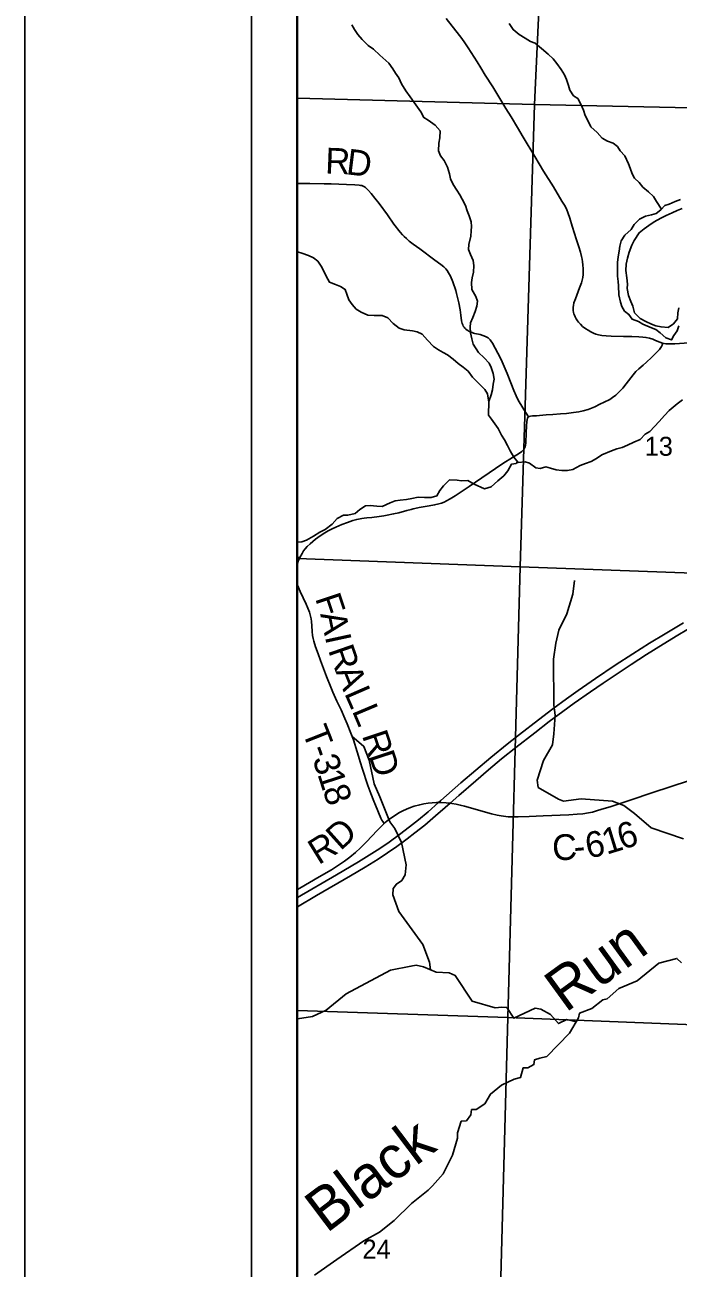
# Model space of a CAD drawing. Extents: x 0 to 34, y 0 to 22.
# Drawn here: x 2 to 3.441, y 16.998 to 19.741 of the extents above; entities that cross this region are included whole.
import ezdxf

# ---------------------------------------------------------------- set-up
doc = ezdxf.new("R2010")
doc.units = 0
for name, color, linetype in [('GM_X_County', 7, 'Continuous'), ('GM_X_County_Road', 7, 'Continuous'), ('GM_X_County_Road_Text', 7, 'Continuous'), ('GM_X_Minor_River', 7, 'Continuous'), ('GM_X_Minor_River_Text', 7, 'Continuous'), ('GM_X_Section', 7, 'Continuous'), ('GM_X_Section_Text', 7, 'Continuous'), ('GM_X_State_Route', 7, 'Continuous'), ('GM_X_Township', 7, 'Continuous'), ('GM_X_Township_Road', 7, 'Continuous'), ('GM_X_Township_Road_Text', 7, 'Continuous'), ('SH_Border', 7, 'Continuous'), ('SH_Data', 7, 'Continuous')]:
    doc.layers.add(name, color=color, linetype=linetype)

msp = doc.modelspace()

# ---------------------------------------------------------------- linework, layer by layer
at = {"layer": 'GM_X_County'}
msp.add_lwpolyline([(7.0736, 21.2003), (2.6013, 21.2003), (2.6013, 14.4003), (9.4013, 14.4003), (9.4013, 21.1598)], dxfattribs=at)
at = {"layer": 'GM_X_County_Road'}
for points in [[(2.9295, 19.7551), (2.9428, 19.7379), (2.9619, 19.7134), (2.9692, 19.7034), (2.9779, 19.6905), (2.9846, 19.6801), (2.9979, 19.6591), (3.0061, 19.646), (3.0157, 19.6301), (3.0321, 19.6038), (3.0496, 19.575), (3.0611, 19.5564), (3.0724, 19.5382), (3.0867, 19.5143), (3.0993, 19.4934), (3.1246, 19.4503), (3.1438, 19.4182), (3.1661, 19.3834), (3.1848, 19.3521), (3.1915, 19.341), (3.1957, 19.3328), (3.1979, 19.3268), (3.2023, 19.314), (3.2071, 19.2969), (3.2122, 19.2803), (3.2159, 19.2684), (3.2217, 19.2508), (3.2256, 19.239), (3.228, 19.23), (3.2293, 19.224), (3.2303, 19.2178), (3.231, 19.2117), (3.2315, 19.2023), (3.2316, 19.1961), (3.2312, 19.1898), (3.2305, 19.1836), (3.2292, 19.1775), (3.2275, 19.1719), (3.2236, 19.1605), (3.2147, 19.1363), (3.2113, 19.1273), (3.21, 19.1216), (3.2096, 19.1179), (3.2094, 19.1143), (3.2094, 19.1105), (3.2102, 19.1063), (3.2112, 19.1029), (3.2123, 19.1002), (3.2139, 19.0964), (3.2161, 19.0923), (3.2176, 19.0897), (3.2191, 19.0876), (3.2213, 19.0847), (3.2254, 19.0802), (3.2302, 19.0756), (3.2371, 19.0703), (3.2425, 19.0669), (3.2484, 19.0632), (3.2544, 19.0603), (3.2597, 19.0584), (3.2654, 19.0568), (3.2729, 19.0556), (3.2821, 19.0547), (3.2934, 19.0542), (3.3207, 19.0535), (3.3388, 19.0529), (3.3542, 19.0522), (3.3628, 19.0521), (3.37, 19.0513), (3.3778, 19.0495), (3.3852, 19.0471), (3.3912, 19.0445), (3.4005, 19.0405), (3.4065, 19.0384), (3.4074, 19.0382)], [(3.4074, 19.0382), (3.4138, 19.0371), (3.4197, 19.0369), (3.4259, 19.0371), (3.4336, 19.0374), (3.4746, 19.0397)], [(3.1436, 17.9953), (3.1996, 17.9978), (3.2183, 17.999), (3.2306, 18.0004), (3.243, 18.0023), (3.2522, 18.0041), (3.2612, 18.0065), (3.273, 18.0102), (3.2908, 18.0158), (3.3439, 18.0333), (3.3763, 18.044), (3.4324, 18.0627), (3.4797, 18.0779), (3.5149, 18.0901), (3.5266, 18.0945), (3.5349, 18.0983)], [(2.7928, 17.9787), (2.795, 17.9807), (2.8021, 17.9865), (2.8096, 17.9921), (2.8172, 17.9973), (2.8252, 18.0021), (2.8334, 18.0064), (2.8418, 18.0104), (2.8503, 18.0138), (2.8591, 18.0168), (2.871, 18.0202), (2.8801, 18.0221), (2.8893, 18.0236), (2.8985, 18.0245), (2.9078, 18.025), (2.9124, 18.025), (2.9125, 18.025), (2.9172, 18.025), (2.9296, 18.0243), (2.9378, 18.0233), (2.9421, 18.0228), (2.9513, 18.0213), (2.9605, 18.0195), (2.9695, 18.0171), (3.0294, 18.0004), (3.0415, 17.9974), (3.0507, 17.9957), (3.0661, 17.9938), (3.0754, 17.9932), (3.0879, 17.9931), (3.1127, 17.994), (3.1436, 17.9953)], [(2.6013, 17.8328), (2.6064, 17.8357), (2.6494, 17.8607), (2.6761, 17.8766), (2.6919, 17.8866), (2.7047, 17.8954), (2.7171, 17.9048), (2.7291, 17.9148), (2.7406, 17.9253), (2.7538, 17.9384), (2.7773, 17.9633), (2.7881, 17.9744), (2.7928, 17.9787)]]:
    msp.add_lwpolyline(points, dxfattribs=at)
at = {"layer": 'GM_X_Minor_River'}
for points in [[(2.9365, 19.412), (2.9326, 19.4268), (2.9246, 19.4415), (2.9169, 19.4518), (2.9127, 19.4631), (2.9134, 19.4798), (2.9153, 19.4916), (2.916, 19.5068), (2.9053, 19.5197), (2.8893, 19.5303), (2.8798, 19.5363), (2.8733, 19.5492), (2.8588, 19.5696), (2.85, 19.5821), (2.8405, 19.595), (2.8309, 19.6109), (2.8252, 19.6238), (2.8179, 19.6344), (2.8114, 19.6439), (2.8026, 19.656), (2.7828, 19.6742), (2.7687, 19.687), (2.757, 19.6953), (2.7444, 19.7086), (2.7345, 19.7196), (2.7272, 19.7305), (2.7211, 19.7412)], [(3.4044, 19.3345), (3.3932, 19.3512), (3.3867, 19.3618), (3.376, 19.3728), (3.363, 19.383), (3.355, 19.3929), (3.3448, 19.4027), (3.3398, 19.4125), (3.3352, 19.4243), (3.3317, 19.4345), (3.3233, 19.4516), (3.313, 19.463), (3.3069, 19.4728), (3.2974, 19.48), (3.2852, 19.4841), (3.2731, 19.4909), (3.2624, 19.5034), (3.2487, 19.5159), (3.2418, 19.5299), (3.2357, 19.5409), (3.2322, 19.5523), (3.2265, 19.5659), (3.22, 19.5781), (3.2101, 19.5845), (3.202, 19.5966), (3.199, 19.6068), (3.1947, 19.6201), (3.1905, 19.6303), (3.1833, 19.6421), (3.1733, 19.6553), (3.1653, 19.6656), (3.1543, 19.6762), (3.1398, 19.689), (3.1253, 19.7004), (3.1155, 19.7041), (3.1037, 19.7113), (3.0904, 19.7196), (3.077, 19.7306), (3.0683, 19.7435)], [(3.4507, 18.9137), (3.439, 18.9045), (3.4216, 18.8897), (3.4107, 18.8786), (3.399, 18.866), (3.3888, 18.8546), (3.3786, 18.8436), (3.3683, 18.8375), (3.3574, 18.8257), (3.343, 18.8199), (3.329, 18.8134), (3.3176, 18.8085), (3.3055, 18.8054), (3.2938, 18.8012), (3.2725, 18.792), (3.2608, 18.7843), (3.2491, 18.7775), (3.237, 18.7733), (3.2252, 18.7687), (3.2089, 18.7595), (3.1968, 18.7579), (3.1843, 18.7575), (3.1721, 18.7594), (3.1596, 18.7631), (3.1493, 18.7657), (3.1368, 18.7619), (3.127, 18.7638), (3.1133, 18.774), (3.1034, 18.7766), (3.0878, 18.775), (3.0787, 18.7868), (3.0703, 18.8012), (3.0645, 18.8129), (3.0577, 18.825), (3.0512, 18.8357), (3.0439, 18.8504), (3.0366, 18.8603), (3.0294, 18.8705), (3.0229, 18.88), (3.0235, 18.91), (3.0288, 18.9248), (3.0318, 18.9354), (3.0332, 18.948), (3.0355, 18.9594), (3.0331, 18.9719), (3.0285, 18.9852), (3.0243, 18.9946), (3.0133, 19.006), (3.0007, 19.0181), (2.9889, 19.0363), (2.9858, 19.0484), (2.9831, 19.0613), (2.9826, 19.0738), (2.9833, 19.0833), (2.9882, 19.0955), (2.9931, 19.1081), (2.9972, 19.1202), (2.9987, 19.1312), (2.9949, 19.1418), (2.9861, 19.1566), (2.9849, 19.1722), (2.9864, 19.1824), (2.9897, 19.195), (2.99, 19.2098), (2.9888, 19.2208), (2.9831, 19.2341), (2.9785, 19.2451), (2.9792, 19.2561), (2.9841, 19.2747), (2.9848, 19.2861), (2.9855, 19.2963), (2.9847, 19.3066), (2.9801, 19.3195), (2.9759, 19.3305), (2.9717, 19.3422), (2.9644, 19.3562), (2.9598, 19.3661), (2.9525, 19.3763), (2.9449, 19.3885), (2.9388, 19.401), (2.9365, 19.412)], [(3.4459, 19.3552), (3.4345, 19.3514), (3.4213, 19.3452), (3.4118, 19.3425), (3.4027, 19.3326), (3.3925, 19.3243), (3.3819, 19.3216), (3.369, 19.3185), (3.3561, 19.3124), (3.3437, 19.3002), (3.3376, 19.2892), (3.3236, 19.277), (3.3157, 19.2644), (3.3124, 19.2526), (3.3113, 19.2416), (3.3091, 19.2287), (3.3076, 19.2165), (3.3069, 19.2067), (3.3069, 19.1957), (3.3073, 19.1862)], [(3.4427, 19.1164), (3.4401, 19.1054), (3.4398, 19.0921), (3.4307, 19.081), (3.419, 19.0734), (3.4034, 19.0745), (3.392, 19.0771), (3.3825, 19.0801), (3.37, 19.0861), (3.3574, 19.0933), (3.3448, 19.1058), (3.341, 19.1202), (3.3364, 19.1305), (3.3314, 19.1437), (3.3287, 19.1589), (3.3294, 19.1688), (3.3282, 19.1828), (3.3255, 19.1988), (3.3262, 19.2132), (3.3296, 19.2261), (3.3333, 19.239), (3.3389, 19.2546), (3.3438, 19.2653), (3.3547, 19.282), (3.3661, 19.2911), (3.3767, 19.2984), (3.388, 19.306), (3.4032, 19.314), (3.4149, 19.3205), (3.4278, 19.3259), (3.4388, 19.3316), (3.4501, 19.3358)], [(3.0235, 18.9081), (3.0208, 18.9267), (3.0143, 18.9365), (3.001, 18.9501), (2.9876, 18.9634), (2.9781, 18.9766), (2.9667, 18.9857), (2.956, 18.9937), (2.945, 19.0035), (2.9324, 19.0129), (2.9229, 19.0178), (2.9123, 19.0235), (2.9012, 19.0314), (2.8883, 19.0451), (2.8765, 19.0583), (2.8654, 19.0636), (2.8548, 19.0654), (2.837, 19.068), (2.8259, 19.0714), (2.8122, 19.082), (2.8004, 19.0945), (2.7879, 19.0998), (2.7708, 19.0993), (2.7564, 19.1004), (2.7416, 19.1068), (2.7309, 19.1136), (2.7218, 19.1242), (2.7145, 19.1341), (2.7099, 19.1466), (2.7064, 19.1572), (2.6966, 19.1636), (2.6855, 19.1681), (2.6719, 19.173), (2.6646, 19.1863), (2.6604, 19.1962), (2.6539, 19.2083), (2.6462, 19.2193), (2.6367, 19.2268), (2.6257, 19.2321), (2.6109, 19.237), (2.6013, 19.2403)], [(3.3073, 19.1862), (3.3085, 19.1744), (3.3093, 19.1649), (3.3102, 19.1452), (3.3136, 19.1289), (3.3171, 19.1194), (3.3224, 19.1095), (3.3323, 19.102), (3.3396, 19.0914), (3.3537, 19.0865), (3.3632, 19.0808), (3.3822, 19.0725), (3.3917, 19.0688), (3.4012, 19.0616), (3.4141, 19.0502), (3.4267, 19.0457), (3.4316, 19.0556), (3.4387, 19.0659), (3.4429, 19.0765)], [(3.0866, 18.7766), (3.0837, 18.7727), (3.0738, 18.7716), (3.0655, 18.7567), (3.0565, 18.7461), (3.0436, 18.7346), (3.0285, 18.7213), (3.0137, 18.7171), (2.9913, 18.7276), (2.9772, 18.7356), (2.9632, 18.7348), (2.9537, 18.7362), (2.937, 18.7369), (2.9234, 18.7236), (2.9151, 18.7133), (2.909, 18.7019), (2.8962, 18.6977), (2.8817, 18.698), (2.8677, 18.6984), (2.8537, 18.696), (2.8415, 18.6933), (2.8275, 18.6925), (2.8169, 18.691), (2.8055, 18.6864), (2.7885, 18.6784), (2.7763, 18.6787), (2.7615, 18.6806), (2.7517, 18.6798), (2.7388, 18.6714), (2.7286, 18.6626), (2.7123, 18.6587), (2.7028, 18.6591), (2.6892, 18.6518), (2.6779, 18.6393), (2.6627, 18.6275), (2.651, 18.6213), (2.6366, 18.6126), (2.6211, 18.6038), (2.6109, 18.6003), (2.6013, 18.5997)], [(3.4526, 17.9447), (3.3812, 17.9695), (3.3448, 18.0009), (3.3216, 18.0183), (3.2962, 18.0281), (3.2268, 18.0332), (3.1882, 18.0281), (3.1772, 18.0323), (3.132, 18.0583), (3.13, 18.0746), (3.1439, 18.1175), (3.1639, 18.1525), (3.1668, 18.1767), (3.1697, 18.2177), (3.167, 18.2397), (3.1659, 18.3414), (3.1715, 18.3763), (3.1778, 18.4055), (3.1952, 18.4416), (3.2087, 18.4849), (3.2127, 18.5149)], [(2.8949, 17.6561), (2.8922, 17.6725), (2.8781, 17.7116), (2.8252, 17.7846), (2.8118, 17.821), (2.8121, 17.835), (2.8197, 17.8449), (2.8314, 17.8529), (2.8389, 17.8654), (2.8408, 17.8875), (2.8307, 17.9367), (2.8159, 17.9678), (2.8052, 17.9826), (2.783, 18.0375), (2.7704, 18.0663), (2.7593, 18.1186), (2.7478, 18.1489), (2.7216, 18.1716)], [(3.2158, 17.5408), (3.1958, 17.546), (3.1773, 17.5372), (3.1598, 17.5573), (3.1385, 17.569), (3.126, 17.5712), (3.0783, 17.5491), (3.0631, 17.5729), (3.0521, 17.5733), (3.0373, 17.5717), (2.9865, 17.5867), (2.9492, 17.6435), (2.9363, 17.6495), (2.9075, 17.651), (2.879, 17.6626), (2.8631, 17.666), (2.8517, 17.6637), (2.8063, 17.6548), (2.7091, 17.6029), (2.6645, 17.5671), (2.6342, 17.553), (2.6013, 17.5477)], [(3.4481, 17.6712), (3.4383, 17.6811), (3.3981, 17.6707), (3.3505, 17.6319), (3.31, 17.6147), (3.2847, 17.5922), (3.2749, 17.5895), (3.251, 17.5709), (3.2238, 17.5605), (3.2212, 17.5503), (3.2016, 17.5161), (3.1513, 17.4643), (3.1362, 17.4613), (3.1245, 17.4574), (3.123, 17.4468), (3.1094, 17.4399), (3.0991, 17.4395), (3.0935, 17.4186), (3.0791, 17.4148), (3.0515, 17.4014), (3.0269, 17.3816), (3.0145, 17.3604), (2.9956, 17.3478), (2.9854, 17.3474), (2.9839, 17.336), (2.9741, 17.3227), (2.9627, 17.3219), (2.9541, 17.2961), (2.9545, 17.2843), (2.9436, 17.2471), (2.9229, 17.2061), (2.8995, 17.1791), (2.8893, 17.1699), (2.853, 17.1406), (2.8149, 17.1026), (2.7824, 17.0767), (2.7476, 17.0576), (2.6882, 17.0164), (2.6391, 16.9821)]]:
    msp.add_lwpolyline(points, dxfattribs=at)
at = {"layer": 'GM_X_Section'}
for p, q in [((2.6013, 20.5903), (2.6013, 19.5793)), ((2.6013, 19.5793), (2.6013, 18.5632)), ((2.6013, 18.5632), (2.6013, 17.5659)), ((2.6013, 17.5659), (2.6013, 16.5373))]:
    msp.add_line(p, q, dxfattribs=at)
for points in [[(2.6013, 19.5793), (3.1241, 19.5651), (3.1703, 20.5686), (2.6013, 20.5903)], [(2.6013, 18.5632), (3.0927, 18.5447), (3.1241, 19.5651), (2.6013, 19.5793)], [(2.6013, 17.5659), (3.0654, 17.5504), (3.0927, 18.5447), (2.6013, 18.5632)], [(2.6013, 16.5373), (3.0372, 16.514), (3.0654, 17.5504), (2.6013, 17.5659)]]:
    msp.add_lwpolyline(points, dxfattribs=at)
for points in [[(3.1703, 20.5686), (3.6876, 20.5473), (3.6799, 20.3833), (3.6562, 19.8796), (3.6414, 19.554), (3.1241, 19.5651)], [(3.1241, 19.5651), (3.6414, 19.554), (3.6343, 19.3746), (3.6142, 18.8692), (4.1194, 18.8444), (4.1166, 18.5074), (3.0927, 18.5447)], [(4.1166, 18.5074), (4.0746, 17.5111), (3.0654, 17.5504), (3.0927, 18.5447)], [(3.0654, 17.5504), (4.0746, 17.5111), (4.0244, 16.4784), (4.0204, 16.4785), (3.5484, 16.5002), (3.0372, 16.514)]]:
    msp.add_lwpolyline(points, close=True, dxfattribs=at)
at = {"layer": 'GM_X_State_Route'}
for points in [[(2.6013, 17.8156), (2.6876, 17.8657), (2.7359, 17.8939), (2.7598, 17.9085), (2.7833, 17.9237), (2.8038, 17.9378), (2.8264, 17.9542), (2.8486, 17.9712), (2.868, 17.9868), (2.8894, 18.0048), (2.9124, 18.025), (2.9174, 18.0294), (2.9617, 18.0683), (2.9947, 18.0966), (3.028, 18.1246), (3.0641, 18.154), (3.0909, 18.1753), (3.1327, 18.2075), (3.1649, 18.2318), (3.195, 18.2538), (3.2203, 18.2719), (3.2586, 18.2983), (3.3023, 18.3278), (3.3413, 18.3532), (3.3781, 18.3764), (3.4125, 18.3974), (3.4525, 18.4212)], [(2.9268, 18.0137), (2.9378, 18.0233), (2.9572, 18.0403), (2.9945, 18.0731), (3.0228, 18.0974), (3.0515, 18.1212), (3.0831, 18.1464), (3.1247, 18.179), (3.1568, 18.2035), (3.1867, 18.2258), (3.2119, 18.2439), (3.2474, 18.2691), (3.2755, 18.2885), (3.3375, 18.3298), (3.3714, 18.3517), (3.4082, 18.3747), (3.4401, 18.3941), (3.4803, 18.4176)], [(2.6013, 17.7952), (2.6431, 17.8196), (2.7182, 17.8635), (2.7503, 17.8824), (2.7794, 17.9004), (2.8001, 17.914), (2.8205, 17.9281), (2.8431, 17.9446), (2.8603, 17.9578), (2.8821, 17.9754), (2.9058, 17.9953), (2.9268, 18.0137)]]:
    msp.add_lwpolyline(points, dxfattribs=at)
at = {"layer": 'GM_X_Township'}
msp.add_lwpolyline([(6.2234, 21.2003), (2.6013, 21.2003), (2.6013, 16.5379)], dxfattribs=at)
at = {"layer": 'GM_X_Township_Road'}
for points in [[(2.6013, 19.3907), (2.6289, 19.3906), (2.6599, 19.3901), (2.6754, 19.3899), (2.7095, 19.3888), (2.7281, 19.388), (2.7374, 19.3871), (2.7405, 19.3867), (2.7435, 19.3861), (2.7463, 19.3851), (2.749, 19.3838), (2.7516, 19.382), (2.7539, 19.38), (2.7581, 19.3755), (2.7641, 19.3685), (2.7718, 19.3588), (2.7814, 19.3465), (2.7999, 19.3217), (2.8142, 19.3014), (2.8282, 19.2831), (2.833, 19.2779), (2.8368, 19.2737), (2.8415, 19.2695), (2.848, 19.2639), (2.8563, 19.2573), (2.8711, 19.2464), (2.9046, 19.222), (2.9178, 19.212), (2.9244, 19.2068), (2.9283, 19.2028), (2.9314, 19.199), (2.9348, 19.194), (2.9386, 19.1861), (2.9439, 19.1736), (2.9503, 19.155), (2.9524, 19.1483), (2.9545, 19.1396), (2.9572, 19.1276), (2.9599, 19.1124), (2.9617, 19.1003), (2.9634, 19.0881), (2.9648, 19.0821), (2.9658, 19.0792), (2.9671, 19.0764), (2.9687, 19.0738), (2.9707, 19.0714), (2.9729, 19.0693), (2.9755, 19.0675), (2.9809, 19.0645), (2.9865, 19.0618), (2.9894, 19.0607), (2.9924, 19.0598), (3.0045, 19.0573), (3.0105, 19.0557), (3.0163, 19.0534), (3.0191, 19.052), (3.0217, 19.0503), (3.024, 19.0483), (3.0262, 19.0461), (3.0281, 19.0436), (3.0313, 19.0384), (3.0434, 19.0167), (3.049, 19.0056), (3.0529, 18.9972), (3.0636, 18.9713), (3.0717, 18.9512), (3.0785, 18.9338), (3.0835, 18.9225), (3.0892, 18.9115), (3.0939, 18.9034), (3.1009, 18.892), (3.1112, 18.8759)], [(3.1112, 18.8759), (3.1121, 18.8765), (3.1156, 18.8776), (3.1197, 18.878), (3.1286, 18.8783), (3.1355, 18.8786), (3.1496, 18.8801), (3.1647, 18.8815), (3.1813, 18.8826), (3.1948, 18.8836), (3.21, 18.8853), (3.2219, 18.8871), (3.2314, 18.889), (3.2425, 18.8924), (3.25, 18.895), (3.2574, 18.8984), (3.2684, 18.9039), (3.2778, 18.9087), (3.2901, 18.9146), (3.2962, 18.9185), (3.3035, 18.924), (3.3082, 18.9281), (3.3126, 18.9325), (3.3188, 18.9394), (3.3267, 18.949), (3.342, 18.9686), (3.348, 18.9757), (3.3546, 18.9822), (3.3641, 18.9902), (3.3711, 18.9963), (3.3826, 19.0067), (3.3913, 19.0155), (3.3996, 19.0247), (3.403, 19.0288), (3.4046, 19.0314), (3.406, 19.0343), (3.4074, 19.0382)], [(2.6069, 18.566), (2.6114, 18.5746), (2.6145, 18.58), (2.6182, 18.585), (2.6224, 18.5896), (2.6292, 18.5959), (2.6412, 18.6058), (2.6511, 18.6132), (2.6615, 18.62), (2.6694, 18.6248), (2.6777, 18.629), (2.6862, 18.6329), (2.6995, 18.6385), (2.7116, 18.6432), (2.7236, 18.6474), (2.7322, 18.6495), (2.7433, 18.6518), (2.7488, 18.6527), (2.7544, 18.6531), (2.7651, 18.6541), (2.7815, 18.6561), (2.7916, 18.6578), (2.7991, 18.6591), (2.8132, 18.6617), (2.8248, 18.6643), (2.8428, 18.6692), (2.852, 18.6719), (2.8564, 18.6731), (2.8603, 18.674), (2.8701, 18.676), (2.8916, 18.6794), (2.9038, 18.6816), (2.9129, 18.6837), (2.9188, 18.6855), (2.9246, 18.6878), (2.9302, 18.6905), (2.9384, 18.695), (2.949, 18.7015), (2.9799, 18.7223), (3.0083, 18.7414), (3.0546, 18.7727), (3.0753, 18.7865), (3.0912, 18.7962), (3.0964, 18.7997), (3.0988, 18.8016), (3.1009, 18.8039), (3.1024, 18.8066), (3.1034, 18.8095), (3.1041, 18.8126), (3.1048, 18.8187), (3.1055, 18.8405), (3.1064, 18.856), (3.1074, 18.8652), (3.1082, 18.8701), (3.109, 18.8727), (3.11, 18.875), (3.1112, 18.8759)], [(2.6069, 18.566), (2.6013, 18.5662)], [(2.6013, 18.5521), (2.6013, 18.5523), (2.6032, 18.5576), (2.6051, 18.5624), (2.6069, 18.566)], [(2.7928, 17.9787), (2.7893, 17.9832), (2.7875, 17.9861), (2.7852, 17.9906), (2.7734, 18.0192), (2.7699, 18.0278), (2.7631, 18.0452), (2.7568, 18.0627), (2.7442, 18.1011), (2.7405, 18.1129), (2.7329, 18.1365), (2.7246, 18.1632), (2.7193, 18.1778), (2.7108, 18.1985), (2.7057, 18.2101), (2.6975, 18.2292), (2.6884, 18.2488), (2.6794, 18.2684), (2.6746, 18.2799), (2.6654, 18.303), (2.6523, 18.3386), (2.6469, 18.3534), (2.6412, 18.3682), (2.6372, 18.3812), (2.6356, 18.3871), (2.6346, 18.3932), (2.6337, 18.4025), (2.6331, 18.4149), (2.6324, 18.4242), (2.6316, 18.4304), (2.6303, 18.4364), (2.6276, 18.4453), (2.6243, 18.454), (2.6206, 18.4625), (2.6138, 18.4765), (2.607, 18.4905), (2.6034, 18.4991), (2.6013, 18.5049), (2.6013, 18.5051)]]:
    msp.add_lwpolyline(points, dxfattribs=at)
at = {"layer": 'SH_Border'}
msp.add_lwpolyline([(2, 21.5), (33.5, 21.5), (33.5, 0.5), (2, 0.5)], close=True, dxfattribs=at)
at = {"layer": 'SH_Data'}
for p, q in [((2.5, 21.2997), (2.5, 14.2997)), ((2.6, 21.1997), (2.6, 14.3997))]:
    msp.add_line(p, q, dxfattribs=at)

# ---------------------------------------------------------------- texts
at = {"layer": 'GM_X_County_Road_Text'}
for s, rotation, p in [('D', 41.8479, (2.6961, 17.9173)), ('1', 17.0302, (3.2831, 17.9096)), ('6', 18.112, (3.3174, 17.9202)), ('R', 31.7543, (2.6479, 17.8864)), ('C', 2.7241, (3.1644, 17.8969)), ('6', 9.9535, (3.2414, 17.9018)), ('-', 4.6927, (3.2128, 17.8992))]:
    msp.add_text(s, height=0.0568, rotation=rotation, dxfattribs=at).set_placement(p)
at = {"layer": 'GM_X_Minor_River_Text'}
for s, rotation, p in [('Run', 36.0258, (3.1926, 17.56)), ('Black', 37.0269, (2.6653, 17.0734))]:
    msp.add_text(s, height=0.0947, rotation=rotation, dxfattribs=at).set_placement(p)
at = {"layer": 'GM_X_Section_Text'}
for s, p in [('13', (3.3672, 18.7901)), ('24', (2.7447, 17.0187))]:
    msp.add_text(s, height=0.04186, rotation=0, dxfattribs=at).set_placement(p)
at = {"layer": 'GM_X_Township_Road_Text'}
for s, rotation, p in [('R', 357.7436, (2.6618, 19.4132)), ('D', 352.959, (2.7072, 19.4115)), ('F', 288.483, (2.6397, 18.4758)), ('A', 281.475, (2.6513, 18.4412)), ('I', 282.2015, (2.6615, 18.3914)), ('R', 289.1752, (2.6684, 18.3614)), ('A', 291.7188, (2.6847, 18.3147)), ('L', 293.562, (2.704, 18.2664)), ('L', 292.8328, (2.7209, 18.2276)), ('T', 291.5507, (2.6109, 18.1819)), ('R', 288.5201, (2.7431, 18.1731)), ('3', 288.1848, (2.6339, 18.1212)), ('-', 289.3582, (2.6263, 18.143)), ('D', 288.2898, (2.7579, 18.1289)), ('1', 288.0696, (2.6448, 18.088)), ('8', 289.079, (2.656, 18.0537))]:
    msp.add_text(s, height=0.0568, rotation=rotation, dxfattribs=at).set_placement(p)

doc.saveas('drawing.dxf')
